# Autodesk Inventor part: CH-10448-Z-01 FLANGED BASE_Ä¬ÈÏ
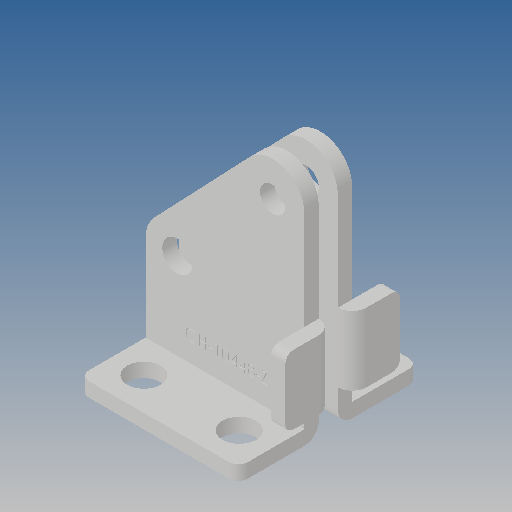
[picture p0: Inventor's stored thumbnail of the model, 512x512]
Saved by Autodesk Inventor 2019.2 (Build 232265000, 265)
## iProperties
Created: 2010-06
Part Number: CH-10448-Z-01 FLANGED BASE_Ä¬ÈÏ
Material: Ogólny
Document SubType Name: Modeling
Designer: CADENGINEERING4
Density: 1 g/cm^3
Appearance: Domyślna
Author: CADENGINEERING4
Revision Number: ÈÎºÎ
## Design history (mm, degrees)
feature "NONE"
feature "NONE:1"
node "Bryła1"
node "Bryła2"
